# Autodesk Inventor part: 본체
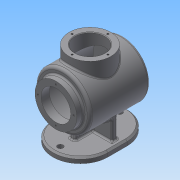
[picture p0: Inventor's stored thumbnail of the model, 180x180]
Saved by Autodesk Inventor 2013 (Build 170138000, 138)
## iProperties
Created: 2016-04
Part Number: 본체
Material: Generic
Document SubType Name: Modeling
Designer: Administrator
Density: 1 g/cm^3
Author: Administrator
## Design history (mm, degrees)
sketch "스케치2"
  geometry: C1 r 50 at (0, 0); 1 further point
  constraints: 1 centre point, 1 coincident
  dimensions: "d10" = 100 diameter of C1
extrude "돌출2" new body sketch "스케치2" distance "d12" = 110; taper "d13" = 0 deg
sketch "스케치3"
  geometry: C1 r 50 at (0, 0) reference; C2 r 38 at (0, 0)
  constraints: 1 centre point, 1 coincident
  dimensions: "d14" = 76 diameter of C2
extrude "돌출3" join sketch "스케치3" distance "d16" = 12; taper "d17" = 0 deg
sketch "스케치4"
  geometry: C1 r 38 at (0, 0) reference; C2 r 27 at (0, 0)
  constraints: 1 centre point, 1 coincident
  dimensions: "d18" = 54 diameter of C2
extrude "돌출4" cut sketch "스케치4" distance "d20" = 15; taper "d21" = 0 deg
node "작업 평면1"
sketch "스케치6"
  geometry: C1 r 27 at (0, 0) reference; C2 r 47 at (0, 0)
  constraints: 1 centre point, 1 coincident
  dimensions: "d23" = 94 diameter of C2
extrude "돌출5" cut sketch "스케치6" distance "d25" = 99.5; taper "d26" = 0 deg
node "작업 평면5"
  node "작업 평면4"
sketch "스케치8"
  geometry: L1 (50, 110)-(-50, 110) reference; C1 r 38 at (0, 60); 1 further point
  constraints: 1 centre point
  dimensions: "d30" = 50 distance from line of L1 C1.centre; "d31" = 0 horizontal distance of point (0, 0) C1.centre; "d32" = 76 diameter of C1
extrude "돌출6" join sketch "스케치8" stored distance "d33" = 99.5; taper "d34" = 0 deg
sketch "스케치9"
  geometry: C1 r 38 at (0, 0) reference; C2 r 27 at (0, 0); 1 further point
  constraints: 1 centre point, 1 coincident
  dimensions: "d35" = 54 diameter of C2
extrude "돌출7" cut sketch "스케치9" stored distance "d37" = 99.5; taper "d38" = 0 deg
sketch "스케치10" dims "d39" = 65
  geometry: C1 r 27 at (0, 0) reference; C2 r 38 at (0, 0) reference; C3 r 2 at (0, 32.5); 2 further points
  constraints: 1 centre point, 1 coincident, 1 vertical alignment, 2 other
  dimensions: "d41" = 0 horizontal distance of C1.centre C3.centre; "d42" = 4 diameter of C3
hole "구멍1" sketch "스케치10" at (0, 32.5) diameter "d43" = 3.242; stored, may be unused: countersink angle "d47" = 90 deg, drill point angle "d49" = 118 deg; dims "d44" = 8, "d45" = 4, "d46" = 2, "d48" = 10
chamfer "모따기1" distance "d53" = 1; stored, may be unused: second distance "d54" = 2, angle "d55" = 45 deg
sketch "스케치11" dims "d56" = 65
  geometry: C1 r 27 at (0, 0) reference; C2 r 38 at (0, 0) reference; C3 r 2 at (0, 32.5); 1 further point
  constraints: 1 centre point, 1 coincident, 1 vertical alignment, 2 other
  dimensions: "d58" = 0 horizontal distance of C1.centre C3.centre; "d59" = 4 diameter of C3
hole "구멍2" sketch "스케치11" at (0, 32.5) diameter "d60" = 3.242; stored, may be unused: countersink angle "d64" = 90 deg, drill point angle "d66" = 118 deg; dims "d61" = 8, "d62" = 4, "d63" = 2, "d65" = 10
node "작업 평면6"
fillet "모깎기1" dims "d71" = 3
fillet "모깎기2" dims "d72" = 5
fillet "모깎기3" dims "d73" = 3
fillet "모깎기4" dims "d74" = 2
node "작업 평면7"
sketch "스케치13"
  geometry: L1 (50, 127.5)-(-50, 127.5); L2 (-50, 127.5)-(-50, -7.5); L3 (-50, -7.5)-(50, -7.5); L4 (50, 0)-(50, 105) reference; L5 (-50, 0)-(-50, 105) reference; L6 (50, 52.5)-(-50, 52.5); L7 (50, 127.5)-(50, -7.5); 1 further point
  constraints: 10 end point, 2 midpoint, 1 collinear, 1 horizontal, 1 parallel, 1 perpendicular
  dimensions: "d80" = 135 distance of L3.end L1.start; "d82" = 100 distance of L2.end L3.end; "d84" = 50 horizontal distance of L2.end point (0, 0); "d85" = 75 distance between parallel lines of L1 L6
extrude "돌출8" join sketch "스케치13" distance "d86" = 10; taper "d87" = 0 deg
fillet "모깎기5" dims "d88" = 50
sketch "스케치14"
  geometry: L1 (-50, -42.5)-(-50, -77.5) reference; L2 (50, -77.5)-(50, -42.5) reference; L3 (-50, -60)-(50, -60); C1 r 5 at (0, -6); C2 r 5 at (0, -114); A1 r 50 centre (0, -77.5) between (-50, -77.5) and (50, -77.5) reference; 1 further point
  constraints: 2 centre point, 2 end point, 2 midpoint
  dimensions: "d89" = 108 distance of C2.centre C1.centre; "d93" = 10 diameter of C2; "d94" = 54 distance from line of L3 C1.centre; "d95" = 0 horizontal distance of point (0, 0) C1.centre; "d96" = 0 horizontal distance of A1.centre C2.centre; "d97" = 10 diameter of C1
extrude "돌출9" cut sketch "스케치14" stored distance "d98" = 10; taper "d99" = 0 deg
chamfer "모따기2" distance "d100" = 3; stored, may be unused: second distance "d101" = 2, angle "d102" = 45 deg
node "작업 평면9"
sketch "스케치16"
  geometry: L1 (-47, -69)-(47, -69) reference; L2 (-40, -69)-(-40, -30); L3 (40, -30)-(40, -69); L4 (-40, -69)-(40, -69); A1 r 50 centre (0, 0) between (-40, -30) and (40, -30) reference; A2 r 50 centre (0, 0) between (-40, -30) and (40, -30); 1 further point
  constraints: 6 end point, 4 point on circle, 2 point on line, 1 centre point, 1 collinear, 1 concentric, 1 parallel, 1 perpendicular
  dimensions: "d109" = 40 distance from line of point (0, 0) L2; "d110" = 40 distance from line of point (0, 0) L3
extrude "돌출10" join sketch "스케치16" stored distance "d111" = 10; taper "d112" = 0 deg
sketch "스케치17"
  geometry: L1 (-50, 0)-(-50, 105) reference; L2 (-30, 60)-(-69, 60) reference; L3 (-69, 124.5)-(-69, 77.5) reference; L4 (-69, 92.5)-(-50, 89.15); L5 (-50, 52.5)-(55.977, 52.5); L6 (-69, 77.5)-(-69, 42.5) reference; 1 further point
  constraints: 4 end point, 2 point on line, 1 midpoint, 1 perpendicular
  dimensions: "d113" = 100 deg angle of L3 L4; "d114" = 40 distance from line of L5 L4.start
feature "리브1" sketch "스케치17" dims "d116" = 1, "d117" = 10, "d118" = 0, "d119" = 0, "d120" = 1, "d121" = 1
fillet "모깎기6" dims "d122" = 3
fillet "모깎기7" dims "d123" = 5
sketch "스케치18"
  geometry: L1 (-29.155, -3.216)-(29.155, -3.216); L2 (29.155, -3.216)-(29.155, 3.216); L3 (29.155, 3.216)-(-29.155, 3.216); L4 (-29.155, 3.216)-(-29.155, -3.216); L5 (-29.155, 0)-(29.155, 0); L6 (0, -3.216)-(0, 3.216); L7 (-38, 65)-(38, 65) reference; L8 (0, 65)-(0, -45); C1 r 50 at (0, 0) reference; 1 further point
  constraints: 6 end point, 5 midpoint, 1 perpendicular, 1 vertical alignment, 3 other
  dimensions: "d124" = 0 horizontal distance of point (0, 0) L6.end; "d125" = 0 distance from line of point (0, 0) L5
extrude "돌출11" join sketch "스케치18" distance "d126" = 0.5; taper "d127" = 0 deg
node "솔리드2"
pattern_circular "원형 패턴1" dims angle "d51" = 360 deg
pattern_circular "원형 패턴2" dims angle "d68" = 360 deg
mirror "대칭1"
other parameters: "d22" = 72, "d28" = -79, "d29" = 144, "d70" = -79, "d75" = -79
